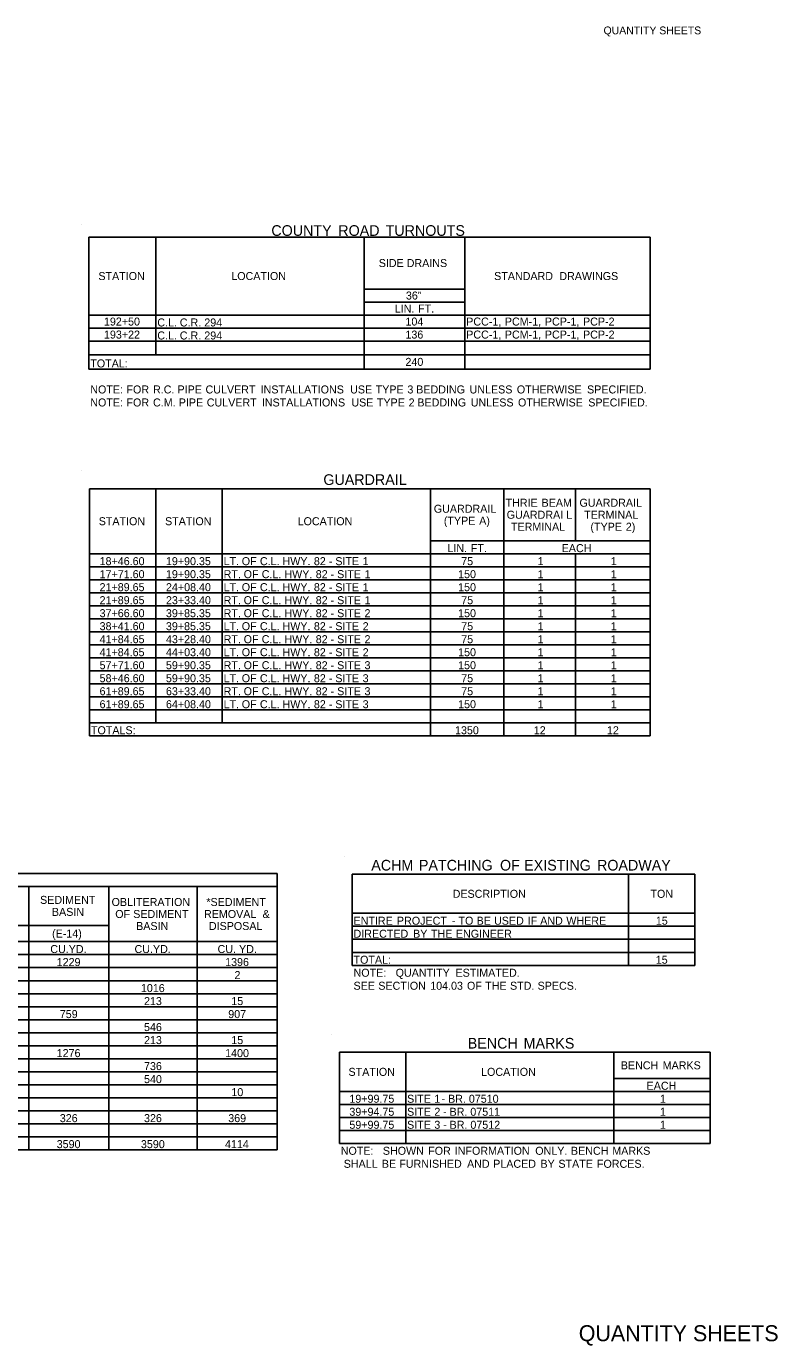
# Model space of a CAD drawing. Extents: x 977434 to 989596, y 1525697 to 1528336.
# Drawn here: x 981852 to 982415, y 1527332 to 1528321 of the extents above; entities that cross this region are included whole.
import ezdxf

# ---------------------------------------------------------------- set-up
doc = ezdxf.new("R2010")
doc.units = 0
for name, color, linetype in [('Default', 7, 'Continuous'), ('R_Border', 7, 'Continuous'), ('R_Border Prem', 7, 'Continuous')]:
    doc.layers.add(name, color=color, linetype=linetype)

msp = doc.modelspace()

# ---------------------------------------------------------------- linework, layer by layer
at = {"layer": 'Default'}
for p, q in [((981899.23, 1528162.97), (982319.94, 1528162.97)), ((981899.23, 1528064.01), (981899.23, 1528162.97)), ((981899.23, 1528064.01), (981899.23, 1528162.97)), ((981949.44, 1528074.73), (981949.44, 1528162.97)), ((982105.44, 1528064.01), (982105.44, 1528162.97)), ((982181, 1528064.01), (982181, 1528162.97)), ((982319.94, 1528064.01), (982319.94, 1528162.97)), ((982319.94, 1528064.01), (982319.94, 1528162.97)), ((982105.44, 1528123.97), (982181, 1528123.97)), ((982181, 1528074.73), (982181, 1528123.97)), ((982105.44, 1528114.22), (982181, 1528114.22)), ((982105.44, 1528114.22), (982181, 1528114.22)), ((982105.44, 1528104.47), (982105.44, 1528114.22)), ((981899.23, 1528104.47), (982319.94, 1528104.47)), ((982181, 1528104.47), (982319.94, 1528104.47)), ((981899.23, 1528094.72), (982319.94, 1528094.72)), ((981899.23, 1528084.97), (982319.94, 1528084.97)), ((982105.44, 1528064.01), (982105.44, 1528084.97)), ((981899.23, 1528074.73), (982319.94, 1528074.73)), ((982105.44, 1528074.73), (982181, 1528074.73)), ((982181, 1528074.73), (982319.94, 1528074.73)), ((981899.23, 1528064.01), (982319.94, 1528064.01)), ((981899.72, 1527974.29), (982319.94, 1527974.29)), ((981899.72, 1527789.04), (981899.72, 1527974.29)), ((981899.72, 1527789.04), (981899.72, 1527974.29)), ((981949.44, 1527798.79), (981949.44, 1527974.29)), ((981999.17, 1527798.79), (981999.17, 1527974.29)), ((982155.17, 1527789.04), (982155.17, 1527974.29)), ((982210.25, 1527789.04), (982210.25, 1527974.29)), ((982263.88, 1527935.29), (982263.88, 1527974.29)), ((982319.94, 1527789.04), (982319.94, 1527974.29)), ((982155.17, 1527935.29), (982319.94, 1527935.29)), ((982210.25, 1527789.04), (982210.25, 1527935.29)), ((982319.94, 1527789.04), (982319.94, 1527935.29)), ((981899.72, 1527925.54), (982319.94, 1527925.54)), ((981949.44, 1527798.79), (981949.44, 1527925.54)), ((981999.17, 1527798.79), (981999.17, 1527925.54)), ((982155.17, 1527789.04), (982155.17, 1527925.54)), ((982263.88, 1527789.04), (982263.88, 1527925.54)), ((982263.88, 1527789.04), (982263.88, 1527925.54)), ((981899.72, 1527915.79), (982319.94, 1527915.79)), ((981899.72, 1527906.04), (982319.94, 1527906.04)), ((981899.72, 1527896.29), (982319.94, 1527896.29)), ((981899.72, 1527886.54), (982319.94, 1527886.54)), ((981899.72, 1527876.79), (982319.94, 1527876.79)), ((981899.72, 1527867.04), (982319.94, 1527867.04)), ((981899.72, 1527857.29), (982319.94, 1527857.29)), ((981899.72, 1527847.54), (982319.94, 1527847.54)), ((981899.72, 1527837.79), (982319.94, 1527837.79)), ((981899.72, 1527828.04), (982319.94, 1527828.04)), ((981899.72, 1527818.29), (982319.94, 1527818.29)), ((981899.72, 1527808.54), (982319.94, 1527808.54)), ((981899.72, 1527798.79), (982319.94, 1527798.79)), ((981899.72, 1527789.04), (982319.94, 1527789.04)), ((980869.9, 1527685.95), (982040.39, 1527685.95)), ((982040.39, 1527478.77), (982040.39, 1527685.95)), ((982096.54, 1527685.26), (982353.46, 1527685.26)), ((982096.54, 1527617.01), (982096.54, 1527685.26)), ((982096.54, 1527617.01), (982096.54, 1527685.26)), ((982303.73, 1527617.01), (982303.73, 1527685.26)), ((982353.46, 1527617.01), (982353.46, 1527685.26)), ((981194.57, 1527676.2), (982040.39, 1527676.2)), ((981854.16, 1527478.77), (981854.16, 1527676.2)), ((981914.12, 1527478.77), (981914.12, 1527676.2)), ((981980.42, 1527478.77), (981980.42, 1527676.2)), ((981614.31, 1527646.95), (981914.12, 1527646.95)), ((981794.2, 1527646.95), (981914.12, 1527646.95)), ((982096.54, 1527656.01), (982353.46, 1527656.01)), ((982303.73, 1527617.01), (982303.73, 1527656.01)), ((982353.46, 1527617.01), (982353.46, 1527656.01)), ((982096.54, 1527646.26), (982353.46, 1527646.26)), ((981194.57, 1527634.77), (982040.39, 1527634.77)), ((981854.16, 1527478.77), (981854.16, 1527634.77)), ((981914.12, 1527634.77), (982040.39, 1527634.77)), ((981914.12, 1527478.77), (981914.12, 1527634.77)), ((981980.42, 1527478.77), (981980.42, 1527634.77)), ((982096.54, 1527636.51), (982353.46, 1527636.51)), ((980869.9, 1527625.02), (982040.39, 1527625.02)), ((982040.39, 1527488.52), (982040.39, 1527625.02)), ((982096.54, 1527626.76), (982353.46, 1527626.76)), ((982096.54, 1527617.01), (982353.46, 1527617.01)), ((980869.9, 1527615.27), (982040.39, 1527615.27)), ((980869.9, 1527605.52), (982040.39, 1527605.52)), ((980869.9, 1527595.77), (982040.39, 1527595.77)), ((980869.9, 1527586.02), (982040.39, 1527586.02)), ((980869.9, 1527576.27), (982040.39, 1527576.27)), ((980869.9, 1527566.52), (982040.39, 1527566.52)), ((980869.9, 1527556.77), (982040.39, 1527556.77)), ((982086.96, 1527551.8), (982364.83, 1527551.8)), ((982086.96, 1527483.55), (982086.96, 1527551.8)), ((982086.96, 1527483.55), (982086.96, 1527551.8)), ((982136.68, 1527483.55), (982136.68, 1527551.8)), ((982292.68, 1527483.55), (982292.68, 1527551.8)), ((982364.83, 1527483.55), (982364.83, 1527551.8)), ((980869.9, 1527547.02), (982040.39, 1527547.02)), ((980869.9, 1527537.27), (982040.39, 1527537.27)), ((982292.68, 1527532.3), (982364.83, 1527532.3)), ((982364.83, 1527483.55), (982364.83, 1527532.3)), ((980869.9, 1527527.52), (982040.39, 1527527.52)), ((982086.96, 1527522.55), (982364.83, 1527522.55)), ((982292.68, 1527483.55), (982292.68, 1527522.55)), ((980869.9, 1527517.77), (982040.39, 1527517.77)), ((982086.96, 1527512.8), (982364.83, 1527512.8)), ((980869.9, 1527508.02), (982040.39, 1527508.02)), ((982086.96, 1527503.05), (982364.83, 1527503.05)), ((980869.9, 1527498.27), (982040.39, 1527498.27)), ((980869.9, 1527488.52), (981914.12, 1527488.52)), ((981736.19, 1527488.52), (981914.12, 1527488.52)), ((981914.12, 1527488.52), (982040.39, 1527488.52)), ((981980.42, 1527488.52), (982040.39, 1527488.52)), ((982086.96, 1527493.3), (982364.83, 1527493.3)), ((980869.9, 1527478.77), (982040.39, 1527478.77)), ((982086.96, 1527483.55), (982364.83, 1527483.55))]:
    msp.add_line(p, q, dxfattribs=at)
at = {"layer": 'R_Border Prem'}
for p, q in [((981893.38, 1528172.72), (981893.38, 1528172.72)), ((981893.87, 1527987.94), (981893.87, 1527987.94)), ((982090.69, 1527698.91), (982090.69, 1527698.91)), ((982081.11, 1527565.45), (982081.11, 1527565.45))]:
    msp.add_line(p, q, dxfattribs=at)

# ---------------------------------------------------------------- texts
at = {"layer": 'Default'}
for s, height, p in [('COUNTY', 8, (982035.92, 1528163.85)), (' ROAD', 8, (982083.13, 1528163.85)), (' TURNOUTS', 8, (982118.6, 1528163.85)), ('SIDE DRAINS', 6, (982116.41, 1528140.47)), ('STATION', 6, (981906.27, 1528130.72)), ('LOCATION', 6, (982005.89, 1528130.72)), ('STANDARD', 6, (982202.91, 1528130.72)), (' DRAWINGS', 6, (982249.54, 1528130.72)), ('36"', 6, (982136.78, 1528116.1)), ('LIN.', 6, (982128.43, 1528106.35)), (' FT.', 6, (982143.69, 1528106.35)), ('192+50', 6, (981910.44, 1528096.6)), ('C.L.', 6, (981950.42, 1528095.92)), (' C.R.', 6, (981965.06, 1528095.92)), (' 294', 6, (981983.42, 1528095.92)), ('104', 6, (982136.44, 1528096.6)), ('PCC-1,', 6, (982181.98, 1528096.6)), (' PCM-1,', 6, (982208.71, 1528096.6)), (' PCP-1,', 6, (982238.71, 1528096.6)), (' PCP-2', 6, (982267.31, 1528096.6)), ('193+22', 6, (981910.46, 1528086.85)), ('C.L.', 6, (981950.42, 1528086.17)), (' C.R.', 6, (981965.06, 1528086.17)), (' 294', 6, (981983.42, 1528086.17)), ('136', 6, (982136.42, 1528086.85)), ('PCC-1,', 6, (982181.98, 1528086.85)), (' PCM-1,', 6, (982208.71, 1528086.85)), (' PCP-1,', 6, (982238.71, 1528086.85)), (' PCP-2', 6, (982267.31, 1528086.85)), ('240', 6, (982136.44, 1528066.37)), ('TOTAL:', 6, (981900.2, 1528065.21)), ('NOTE:', 6, (981900.2, 1528045.71)), (' FOR', 6, (981925.09, 1528045.71)), (' R.C.', 6, (981945, 1528045.71)), (' PIPE', 6, (981963.36, 1528045.71)), (' CULVERT', 6, (981984.35, 1528045.71)), (' INSTALLATIONS', 6, (982025.64, 1528045.71)), (' USE', 6, (982092.75, 1528045.71)), (' TYPE', 6, (982111.87, 1528045.71)), (' 3', 6, (982135.65, 1528045.71)), (' BEDDING', 6, (982142.26, 1528045.71)), (' UNLESS', 6, (982182.26, 1528045.71)), (' OTHERWISE', 6, (982217.7, 1528045.71)), (' SPECIFIED.', 6, (982270.35, 1528045.71)), ('NOTE:', 6, (981900.2, 1528035.96)), (' FOR', 6, (981925.09, 1528035.96)), (' C.M.', 6, (981945, 1528035.96)), (' PIPE', 6, (981964.29, 1528035.96)), (' CULVERT', 6, (981985.28, 1528035.96)), (' INSTALLATIONS', 6, (982026.57, 1528035.96)), (' USE', 6, (982093.68, 1528035.96)), (' TYPE', 6, (982112.8, 1528035.96)), (' 2', 6, (982136.58, 1528035.96)), (' BEDDING', 6, (982143.13, 1528035.96)), (' UNLESS', 6, (982183.13, 1528035.96)), (' OTHERWISE', 6, (982218.57, 1528035.96)), (' SPECIFIED.', 6, (982271.22, 1528035.96)), ('GUARDRAIL', 8, (982074.91, 1527977.12)), ('THRIE', 6, (982211.49, 1527960.79)), (' BEAM', 6, (982236.23, 1527960.79)), ('GUARDRAIL', 6, (982266.89, 1527960.79)), ('GUARDRAIL', 6, (982157.69, 1527956.29)), ('(TYPE', 6, (982165.2, 1527947.29)), (' A)', 6, (982189.48, 1527947.29)), ('GUARDRAI', 6, (982212.31, 1527951.79)), ('L', 6, (982256.95, 1527951.79)), ('TERMINAL', 6, (982270.38, 1527951.79)), ('STATION', 6, (981906.52, 1527946.92)), ('STATION', 6, (981956.24, 1527946.92)), ('LOCATION', 6, (982055.61, 1527946.92)), ('TERMINAL', 6, (982215.54, 1527942.79)), ('(TYPE', 6, (982275.1, 1527942.79)), (' 2)', 6, (982299.38, 1527942.79)), ('LIN.', 6, (982167.92, 1527926.74)), (' FT.', 6, (982183.18, 1527926.74)), ('EACH', 6, (982253.54, 1527926.74)), ('18+46.60', 6, (981907.19, 1527916.99)), ('19+90.35', 6, (981956.88, 1527916.99)), ('LT.', 6, (982000.14, 1527916.99)), (' OF', 6, (982011.52, 1527916.99)), (' C.L.', 6, (982025.11, 1527916.99)), (' HWY.', 6, (982042.07, 1527916.99)), (' 82', 6, (982065.56, 1527916.99)), (' -', 6, (982076.76, 1527916.99)), (' SITE', 6, (982081.62, 1527916.99)), (' 1', 6, (982102.13, 1527916.99)), ('75', 6, (982178.22, 1527916.99)), ('1', 6, (982235.51, 1527916.99)), ('1', 6, (982290.35, 1527916.99)), ('17+71.60', 6, (981907.19, 1527907.24)), ('19+90.35', 6, (981956.88, 1527907.24)), ('RT.', 6, (982000.14, 1527907.24)), (' OF', 6, (982012.92, 1527907.24)), (' C.L.', 6, (982026.5, 1527907.24)), (' HWY.', 6, (982043.47, 1527907.24)), (' 82', 6, (982066.95, 1527907.24)), (' -', 6, (982078.16, 1527907.24)), (' SITE', 6, (982083.01, 1527907.24)), (' 1', 6, (982103.53, 1527907.24)), ('150', 6, (982175.92, 1527907.24)), ('1', 6, (982235.51, 1527907.24)), ('1', 6, (982290.35, 1527907.24)), ('21+89.65', 6, (981907.16, 1527897.49)), ('24+08.40', 6, (981956.92, 1527897.49)), ('LT.', 6, (982000.14, 1527897.49)), (' OF', 6, (982011.52, 1527897.49)), (' C.L.', 6, (982025.11, 1527897.49)), (' HWY.', 6, (982042.07, 1527897.49)), (' 82', 6, (982065.56, 1527897.49)), (' -', 6, (982076.76, 1527897.49)), (' SITE', 6, (982081.62, 1527897.49)), (' 1', 6, (982102.13, 1527897.49)), ('150', 6, (982175.92, 1527897.49)), ('1', 6, (982235.51, 1527897.49)), ('1', 6, (982290.35, 1527897.49)), ('37+66.60', 6, (981907.19, 1527877.99)), ('21+89.65', 6, (981907.16, 1527887.74)), ('39+85.35', 6, (981956.88, 1527877.99)), ('23+33.40', 6, (981956.92, 1527887.74)), ('RT.', 6, (982000.14, 1527887.74)), ('RT.', 6, (982000.14, 1527877.99)), (' OF', 6, (982012.92, 1527887.74)), (' OF', 6, (982012.92, 1527877.99)), (' C.L.', 6, (982026.5, 1527887.74)), (' C.L.', 6, (982026.5, 1527877.99)), (' HWY.', 6, (982043.47, 1527887.74)), (' HWY.', 6, (982043.47, 1527877.99)), (' 82', 6, (982066.95, 1527887.74)), (' 82', 6, (982066.95, 1527877.99)), (' -', 6, (982078.16, 1527887.74)), (' SITE', 6, (982083.01, 1527887.74)), (' SITE', 6, (982083.01, 1527877.99)), (' 2', 6, (982103.53, 1527877.99)), (' 1', 6, (982103.53, 1527887.74)), ('150', 6, (982175.92, 1527877.99)), ('75', 6, (982178.22, 1527887.74)), ('1', 6, (982235.51, 1527887.74)), ('1', 6, (982235.51, 1527877.99)), ('1', 6, (982290.35, 1527887.74)), ('1', 6, (982290.35, 1527877.99)), ('38+41.60', 6, (981907.19, 1527868.24)), ('39+85.35', 6, (981956.88, 1527868.24)), ('LT.', 6, (982000.14, 1527868.24)), (' OF', 6, (982011.52, 1527868.24)), (' C.L.', 6, (982025.11, 1527868.24)), (' HWY.', 6, (982042.07, 1527868.24)), (' 82', 6, (982065.56, 1527868.24)), (' -', 6, (982078.16, 1527877.99)), (' SITE', 6, (982081.62, 1527868.24)), (' 2', 6, (982102.13, 1527868.24)), ('75', 6, (982178.22, 1527868.24)), ('1', 6, (982235.51, 1527868.24)), ('1', 6, (982290.35, 1527868.24)), ('41+84.65', 6, (981907.16, 1527858.49)), ('43+28.40', 6, (981956.92, 1527858.49)), ('RT.', 6, (982000.14, 1527858.49)), (' OF', 6, (982012.92, 1527858.49)), (' C.L.', 6, (982026.5, 1527858.49)), (' HWY.', 6, (982043.47, 1527858.49)), (' 82', 6, (982066.95, 1527858.49)), (' -', 6, (982076.76, 1527868.24)), (' SITE', 6, (982083.01, 1527858.49)), (' 2', 6, (982103.53, 1527858.49)), ('75', 6, (982178.22, 1527858.49)), ('1', 6, (982235.51, 1527858.49)), ('1', 6, (982290.35, 1527858.49)), ('41+84.65', 6, (981907.16, 1527848.74)), ('44+03.40', 6, (981956.92, 1527848.74)), ('LT.', 6, (982000.14, 1527848.74)), (' OF', 6, (982011.52, 1527848.74)), (' C.L.', 6, (982025.11, 1527848.74)), (' HWY.', 6, (982042.07, 1527848.74)), (' 82', 6, (982065.56, 1527848.74)), (' -', 6, (982078.16, 1527858.49)), (' SITE', 6, (982081.62, 1527848.74)), (' 2', 6, (982102.13, 1527848.74)), ('150', 6, (982175.92, 1527848.74)), ('1', 6, (982235.51, 1527848.74)), ('1', 6, (982290.35, 1527848.74)), ('57+71.60', 6, (981907.19, 1527838.99)), ('59+90.35', 6, (981956.88, 1527838.99)), ('RT.', 6, (982000.14, 1527838.99)), (' OF', 6, (982012.92, 1527838.99)), (' C.L.', 6, (982026.5, 1527838.99)), (' HWY.', 6, (982043.47, 1527838.99)), (' 82', 6, (982066.95, 1527838.99)), (' -', 6, (982076.76, 1527848.74)), (' SITE', 6, (982083.01, 1527838.99)), (' 3', 6, (982103.53, 1527838.99)), ('150', 6, (982175.92, 1527838.99)), ('1', 6, (982235.51, 1527838.99)), ('1', 6, (982290.35, 1527838.99)), ('58+46.60', 6, (981907.19, 1527829.24)), ('59+90.35', 6, (981956.88, 1527829.24)), ('LT.', 6, (982000.14, 1527829.24)), (' OF', 6, (982011.52, 1527829.24)), (' C.L.', 6, (982025.11, 1527829.24)), (' HWY.', 6, (982042.07, 1527829.24)), (' 82', 6, (982065.56, 1527829.24)), (' -', 6, (982078.16, 1527838.99)), (' SITE', 6, (982081.62, 1527829.24)), (' 3', 6, (982102.13, 1527829.24)), ('75', 6, (982178.22, 1527829.24)), ('1', 6, (982235.51, 1527829.24)), ('1', 6, (982290.35, 1527829.24)), ('61+89.65', 6, (981907.16, 1527819.49)), ('63+33.40', 6, (981956.92, 1527819.49)), ('RT.', 6, (982000.14, 1527819.49)), (' OF', 6, (982012.92, 1527819.49)), (' C.L.', 6, (982026.5, 1527819.49)), (' HWY.', 6, (982043.47, 1527819.49)), (' 82', 6, (982066.95, 1527819.49)), (' -', 6, (982076.76, 1527829.24)), (' SITE', 6, (982083.01, 1527819.49)), (' 3', 6, (982103.53, 1527819.49)), ('75', 6, (982178.22, 1527819.49)), ('1', 6, (982235.51, 1527819.49)), ('1', 6, (982290.35, 1527819.49)), ('61+89.65', 6, (981907.16, 1527809.74)), ('64+08.40', 6, (981956.92, 1527809.74)), ('LT.', 6, (982000.14, 1527809.74)), (' OF', 6, (982011.52, 1527809.74)), (' C.L.', 6, (982025.11, 1527809.74)), (' HWY.', 6, (982042.07, 1527809.74)), (' 82', 6, (982065.56, 1527809.74)), (' -', 6, (982078.16, 1527819.49)), (' SITE', 6, (982081.62, 1527809.74)), (' 3', 6, (982102.13, 1527809.74)), ('150', 6, (982175.92, 1527809.74)), ('1', 6, (982235.51, 1527809.74)), ('1', 6, (982290.35, 1527809.74)), (' -', 6, (982076.76, 1527809.74)), ('TOTALS:', 6, (981900.69, 1527790.24)), ('1350', 6, (982173.6, 1527790.24)), ('12', 6, (982232.62, 1527790.24)), ('12', 6, (982287.46, 1527790.24)), ('ACHM', 8, (982110.82, 1527688.08)), (' PATCHING', 8, (982143.55, 1527688.08)), (' OF', 8, (982204.35, 1527688.08)), (' EXISTING', 8, (982222.46, 1527688.08)), (' ROADWAY', 8, (982277.07, 1527688.08)), ('SEDIMENT', 6, (981862.57, 1527663.08)), ('OBLITERATION', 6, (981916.17, 1527661.49)), ('*SEDIMENT', 6, (981987.2, 1527661.49)), ('DESCRIPTION', 6, (982171.82, 1527667.63)), ('TON', 6, (982320.08, 1527667.63)), ('BASIN', 6, (981871.44, 1527654.08)), ('OF', 6, (981918.91, 1527652.49)), (' SEDIMENT', 6, (981930.16, 1527652.49)), ('REMOVAL', 6, (981985.45, 1527652.49)), (' &', 6, (982027.12, 1527652.49)), ('BASIN', 6, (981934.57, 1527643.49)), ('DISPOSAL', 6, (981989.1, 1527643.49)), ('ENTIRE', 6, (982097.52, 1527647.46)), (' PROJECT', 6, (982127.82, 1527647.46)), (' -', 6, (982169.11, 1527647.46)), (' TO', 6, (982173.96, 1527647.46)), (' BE', 6, (982187.56, 1527647.46)), (' USED', 6, (982200.62, 1527647.46)), (' IF', 6, (982225.8, 1527647.46)), (' AND', 6, (982235.19, 1527647.46)), (' WHERE', 6, (982254.78, 1527647.46)), ('15', 6, (982324.1, 1527647.46)), ('(E-14)', 6, (981871.56, 1527637.86)), ('DIRECTED', 6, (982097.52, 1527637.71)), (' BY', 6, (982139.93, 1527637.71)), (' THE', 6, (982153.37, 1527637.71)), (' ENGINEER', 6, (982172.02, 1527637.71)), ('CU.YD.', 6, (981870.22, 1527626.22)), ('CU.YD.', 6, (981933.36, 1527626.22)), ('CU.', 6, (981995.61, 1527626.22)), (' YD.', 6, (982009.47, 1527626.22)), ('1229', 6, (981875.01, 1527616.47)), ('1396', 6, (982001.28, 1527616.47)), ('TOTAL:', 6, (982097.52, 1527618.21)), ('15', 6, (982324.06, 1527618.21)), ('2', 6, (982008.3, 1527606.72)), ('NOTE:', 6, (982097.52, 1527608.46)), ('   QUANTITY', 6, (982122.41, 1527608.46)), (' ESTIMATED.', 6, (982171.71, 1527608.46)), ('1016', 6, (981938.14, 1527596.97)), ('SEE', 6, (982097.52, 1527598.71)), (' SECTION', 6, (982113.85, 1527598.71)), (' 104.03', 6, (982152.76, 1527598.71)), (' OF', 6, (982180.33, 1527598.71)), (' THE', 6, (982193.92, 1527598.71)), (' STD.', 6, (982212.57, 1527598.71)), (' SPECS.', 6, (982233.26, 1527598.71)), ('213', 6, (981940.47, 1527587.22)), ('15', 6, (982005.91, 1527587.22)), ('759', 6, (981877.34, 1527577.47)), ('907', 6, (982003.61, 1527577.47)), ('546', 6, (981940.47, 1527567.72)), ('213', 6, (981940.47, 1527557.97)), ('15', 6, (982005.91, 1527557.97)), ('BENCH', 8, (982183.13, 1527554.62)), (' MARKS', 8, (982222.02, 1527554.62)), ('1276', 6, (981875.01, 1527548.22)), ('1400', 6, (982001.29, 1527548.22)), ('736', 6, (981940.47, 1527538.47)), ('STATION', 6, (982093.76, 1527534.17)), ('LOCATION', 6, (982193.13, 1527534.17)), ('BENCH', 6, (982297.85, 1527539.05)), (' MARKS', 6, (982327.01, 1527539.05)), ('540', 6, (981940.49, 1527528.72)), ('EACH', 6, (982317.2, 1527523.75)), ('10', 6, (982005.95, 1527518.97)), ('19+99.75', 6, (982094.4, 1527514)), ('SITE', 6, (982137.66, 1527514)), (' 1', 6, (982155.85, 1527514)), (' BR.', 6, (982166.15, 1527514)), (' 07510', 6, (982181.72, 1527514)), ('1', 6, (982327.2, 1527514)), ('39+94.75', 6, (982094.4, 1527504.25)), ('SITE', 6, (982137.66, 1527504.25)), (' 2', 6, (982155.85, 1527504.25)), (' -', 6, (982161.29, 1527514)), (' BR.', 6, (982167.25, 1527504.25)), (' 07511', 6, (982182.82, 1527504.25)), ('1', 6, (982327.2, 1527504.25)), ('326', 6, (981877.34, 1527499.47)), ('326', 6, (981940.47, 1527499.47)), ('369', 6, (982003.6, 1527499.47)), ('59+99.75', 6, (982094.4, 1527494.5)), ('SITE', 6, (982137.66, 1527494.5)), (' 3', 6, (982155.85, 1527494.5)), (' -', 6, (982162.39, 1527504.25)), (' BR.', 6, (982167.31, 1527494.5)), (' 07512', 6, (982182.88, 1527494.5)), ('1', 6, (982327.2, 1527494.5)), (' -', 6, (982162.45, 1527494.5)), ('3590', 6, (981875.03, 1527479.97)), ('3590', 6, (981938.16, 1527479.97)), ('4114', 6, (982001.18, 1527479.97)), ('NOTE:', 6, (982087.93, 1527475)), ('   SHOWN', 6, (982112.82, 1527475)), (' FOR', 6, (982151.25, 1527475)), (' INFORMATION', 6, (982171.16, 1527475)), (' ONLY.', 6, (982231.49, 1527475)), (' BENCH', 6, (982258.24, 1527475)), (' MARKS', 6, (982289.24, 1527475)), (' SHALL', 6, (982087.93, 1527465.25)), (' BE', 6, (982116.52, 1527465.25)), (' FURNISHED', 6, (982129.59, 1527465.25)), (' AND', 6, (982180.38, 1527465.25)), (' PLACED', 6, (982199.96, 1527465.25)), (' BY', 6, (982235.39, 1527465.25)), (' STATE', 6, (982248.84, 1527465.25)), (' FORCES.', 6, (982277.74, 1527465.25))]:
    msp.add_text(s, height=height, dxfattribs=at).set_placement(p)
at = {"layer": 'R_Border'}
msp.add_text('QUANTITY SHEETS', height=12, rotation=360, dxfattribs=at).set_placement((982266.34, 1527335.24))
at = {"layer": 'R_Border Prem'}
msp.add_text('QUANTITY SHEETS', height=5.862, rotation=360, dxfattribs=at).set_placement((982284.92, 1528314.92))

doc.saveas('drawing.dxf')
